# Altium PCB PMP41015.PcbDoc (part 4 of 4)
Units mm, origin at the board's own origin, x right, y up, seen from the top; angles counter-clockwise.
Board outline 173 x 85 mm, 2 copper layers (Top Layer, Bottom Layer), stack 1.575 mm thick; 89 components, 48 nets, 216 pads, 3458 vias.
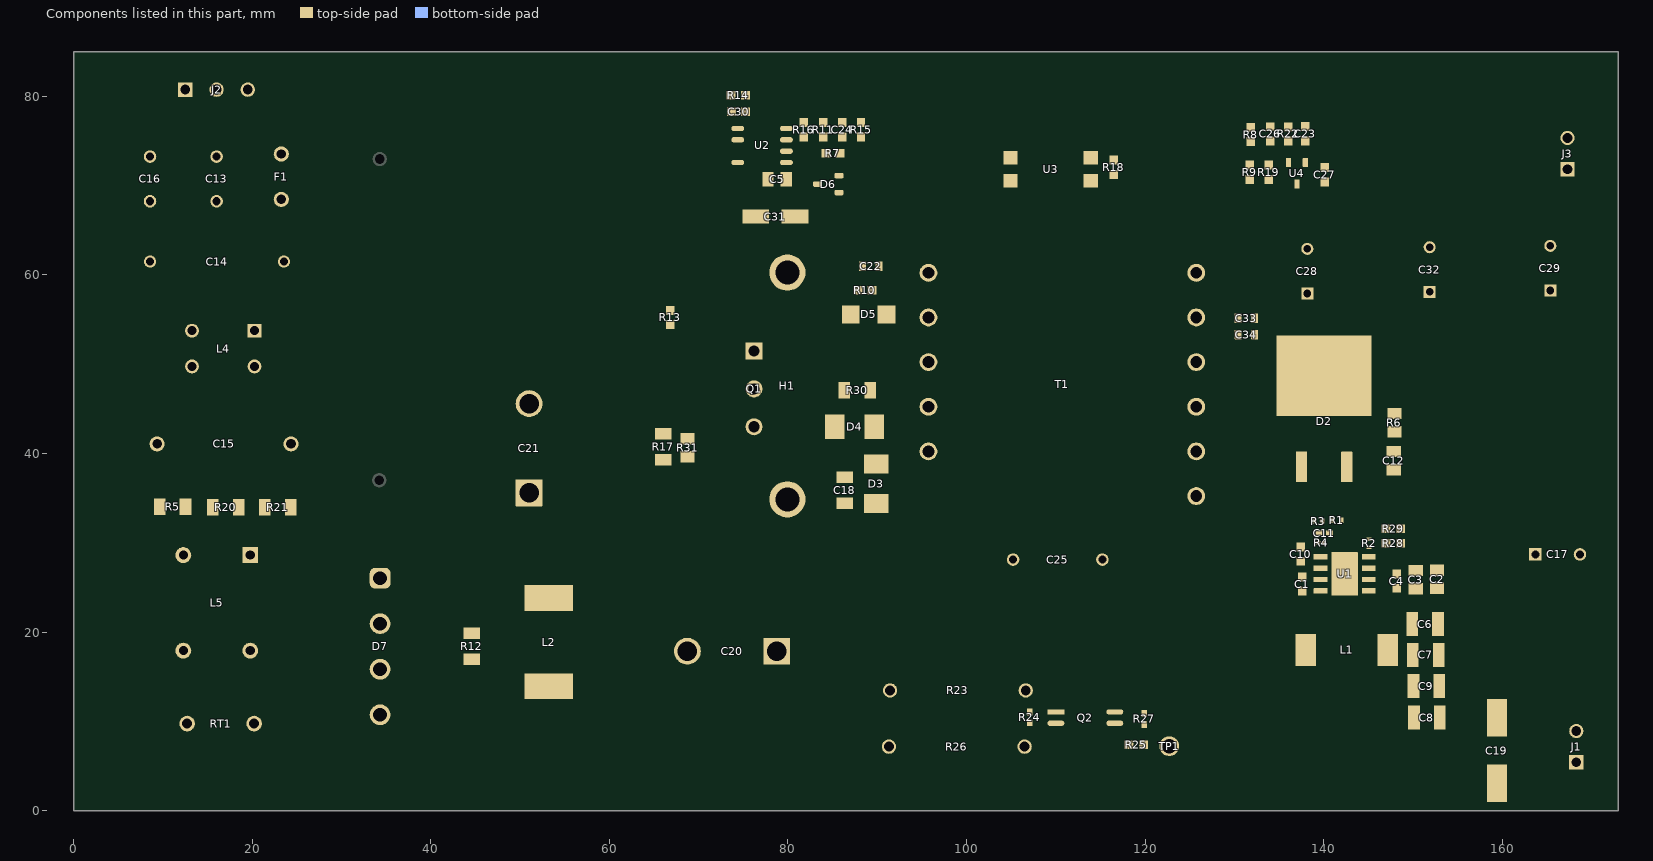
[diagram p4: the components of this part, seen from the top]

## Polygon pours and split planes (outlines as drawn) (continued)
+24V on Top Layer "TOP_LAYER_+24V_P107" (solid, remove dead copper, pour order 107): 159.029,42.8 149.962,42.8 149.962,28.489 149.064,27.592 144.244,27.567 144.244,25.883 165.608,25.883 165.608,31.524 171.978,31.524 171.978,73.101 163.627,73.101 163.627,65.964 167.157,65.964 167.157,60.782 159.029,60.782
PGND on Top Layer "TOP_LAYER_PGND_P042" (solid, remove dead copper, pour order 42): 29.388,24.426 37.084,24.426 37.084,83.657 29.388,83.657
+24V on Top Layer "TOP_LAYER_+24V_P097" (solid, remove dead copper, pour order 97): 128.246,43.355 128.244,57.022 132.105,60.884 159.08,60.884 159.08,54.178 158.27,54.178 158.27,43.355
PGND on Top Layer "TOP_LAYER_PGND_P090" (solid, remove dead copper, pour order 90): 63.525,39.54 63.525,17.412 64.783,16.154 71.857,16.154 73.635,17.932 73.635,26.34 73.635,38.973 72.298,40.31 64.295,40.31
NetQ1_3 on Top Layer "TOP_LAYER_NETQ1_3_P088" (solid, remove dead copper, pour order 88): 65.148,43.49 65.779,44.12 76.616,44.12 77.343,43.393 77.343,41.072 65.683,41.072 65.148,41.526
SGND on Top Layer "TOP_LAYER_SGND_P078" (solid, remove dead copper, pour order 78): 136.728,33.06 136.728,27.991 137.846,26.873 140.386,26.873 140.843,26.416 140.843,24.079 149.225,24.079 149.225,34.468 138.507,34.468
5V on Top Layer "TOP_LAYER_5V_P072" (solid, remove dead copper, pour order 72): 145.288,21.311 146.329,22.352 150.546,22.352 151.138,21.658 151.138,7.788 152.474,6.452 171.78,6.452 171.78,1.016 145.288,1.016 145.288,9.373
SGND on Top Layer "TOP_LAYER_SGND_P070" (solid, remove dead copper, pour order 70): 147.576,25.146 148.034,25.603 158.27,25.603 172.06,25.603 172.06,23.089 146.51,23.089 144.907,21.486 144.907,17.287 144.172,16.435 141.403,16.432 140.843,16.993 140.843,25.146
SGND on Top Layer "TOP_LAYER_SGND_P056" (solid, remove dead copper, pour order 56): 141.351,67.259 142.665,68.665 142.646,82.118 171.978,82.118 171.978,73.838 163.286,73.838 163.307,65.343 166.727,65.343 166.727,61.083 158.488,61.083 132.084,61.126 130.841,60.017 130.841,52.654 123.952,52.654 123.952,63.195 128.016,67.259
NetC12_1 on Top Layer "TOP_LAYER_NETC12_1_P052" (solid, remove dead copper, pour order 52): 123.686,37.401 124.727,36.36 145.599,36.36 145.599,42.8 128.37,42.8 126.947,44.224 126.913,47.244 123.927,47.244 123.612,46.93
SW on Top Layer "TOP_LAYER_SW_P024" (solid, remove dead copper, pour order 24): 139.249,16.154 139.249,23.37 140.056,24.177 140.056,24.943 139.802,25.197 137.135,25.197 136.754,24.816 136.754,16.154
no net on Top Layer "TOP_LAYER_NONET_P036" (solid, remove dead copper, pour order 36): 79.794,70.635 79.825,70.667 79.825,72.59
PGND on Top Layer "TOP_LAYER_PGND_P000" (solid, remove dead copper, pour order 0): 77.025,81.522 77.241,81.737 85.217,81.737 85.217,77.125 84.112,76.02 80.454,76.02 77.026,76.02
PGND on Top Layer "TOP_LAYER_PGND_P040" (solid, remove dead copper, pour order 40): 77.1,71.451 77.1,76.867 78.473,76.867 78.473,75.182 78.473,71.451
PGND on Top Layer "TOP_LAYER_PGND_P048" (solid, remove dead copper, pour order 48): 38.151,83.541 38.151,39.618 58.674,39.618 58.674,83.541

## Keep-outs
Keep-Out Layer:
  text ".Layer_Name" at 14.656,-21.806 h1.52

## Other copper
Top Layer:
  text ".Layer_Name" at 14.656,-21.806 h1.52
Bottom Layer:
  text ".Layer_Name" at 14.656,-21.806 h1.52

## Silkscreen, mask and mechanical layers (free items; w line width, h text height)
Top Overlay:
  text ".Layer_Name" at 14.656,-21.806 h1.52
Bottom Overlay:
  text ".Layer_Name" at 14.656,-21.806 h1.52
Top Paste:
  text ".Layer_Name" at 14.656,-21.806 h1.52
Bottom Paste:
  text ".Layer_Name" at 14.656,-21.806 h1.52
Top Solder:
  rectangle: 144.882,68.665 162.357,78.791
  text ".Layer_Name" at 14.656,-21.806 h1.52
  text ".Layer_Name" at 14.656,-21.806 h1.52
Bottom Solder:
  rectangle: 156.515,12.903 170.891,22.005
  rectangle: 160.02,36.36 165.862,52.313
  rectangle: 133.045,45.734 157.099,57.022
  rectangle: 144.574,68.986 161.315,78.715
  text ".Layer_Name" at 14.656,-21.806 h1.52
Drill Guide:
  text ".Layer_Name" at 14.656,-21.806 h1.52
M1 Board Outline:
  the board outline again, w0.254
  text ".Layer_Name" at 14.656,-21.806 h1.52
M2 Board Dimensions:
  rectangle: 0,-6.985 3.175,-3.81
  rectangle: 3.175,-10.16 12.7,-6.985
  lines w0.178: 0,-6.985 25.4,-6.985 ; 3.175,-10.16 3.175,-3.81 ; 6.35,-10.16 6.35,-3.81 ; 12.7,-10.16 12.7,-3.81 ; 19.05,-10.16 19.05,-3.81 ; 0,-10.16 25.4,-10.16 25.4,-3.81 0,-3.81 0,-10.16
  text ".Layer_Name" at 14.656,-21.806 h1.52
M3 3D STEP Top:
  text ".Layer_Name" at 14.656,-21.806 h1.52
M4 3D STEP Bottom:
  text ".Layer_Name" at 14.656,-21.806 h1.52
M5 Assembly Top:
  lines w0.254: -7.417,-23.626 160.223,-23.626 ; -7.417,-18.462 160.274,-18.462 ; -7.417,-13.297 -7.417,-28.791 94.31,-28.791 160.274,-28.791 160.274,-13.297 -7.404,-13.297 -7.404,-28.791 32.614,-28.791 ; 55.194,-28.791 55.194,-13.297 ; 87.376,-18.462 87.376,-13.297 ; 108.712,-18.462 108.712,-13.297 ; 124.511,-28.956 124.511,-23.804
  text "COMPONENTS MARKED 'DNP' SHOULD NOT BE POPULATED." at 29.299,-8.09 h1.52
  text "ASSEMBLY VARIANT:" at 29.286,-11.024 h1.52
  text ".VariantName" at 55.601,-11.024 h1.52
  text "PCB VIEWED FROM TOP SIDE" at -5.804,-16.654 h1.52
  text "BOARD #:" at 57.099,-16.654 h1.52
  text ".PRJ_Number" at 70.955,-16.654 h1.52
  text "REV:" at 92.405,-16.654 h1.52
  text ".PCB_Rev" at 99.809,-16.654 h1.52
  text "SVN REV:" at 113.69,-16.654 h1.52
  text ".VersionControl_RevNumber" at 126.543,-16.654 h1.52
  text "TID #:" at 57.099,-21.819 h1.52
  text ".TID" at 70.955,-21.819 h1.52
  text "PLOT NAME =" at -5.804,-27.034 h1.52
  text ".plot_File_Name" at 14.656,-27.034 h1.52
  text "GENERATED    :" at 57.15,-27.034 h1.52
  text ".Print_Date" at 79.235,-27.034 h1.52
  text ".Print_Time" at 97.752,-27.034 h1.52
  text "TEXAS INSTRUMENTS" at 129.87,-27.034 h1.52
M6 Assembly Bottom:
  lines w0.254: -7.429,-18.474 160.261,-18.474 ; -7.379,-23.639 160.261,-23.639 ; 28.334,-28.969 28.334,-23.817 ; 44.133,-18.474 44.133,-13.31 ; 65.468,-18.474 65.468,-13.31 ; 97.65,-28.804 97.65,-13.31 ; 120.231,-28.804 160.249,-28.804 160.249,-13.31 -7.429,-13.31 -7.429,-28.804 58.534,-28.804 160.261,-28.804 160.261,-13.31
  text "COMPONENTS MARKED 'DNP' SHOULD NOT BE POPULATED." at 154.991,-8.077 h1.52
  text ".VariantName" at 128.473,-11.024 h1.52
  text "ASSEMBLY VARIANT:" at 154.864,-11.024 h1.52
  text ".VersionControl_RevNumber" at 26.302,-16.667 h1.52
  text "SVN REV:" at 39.154,-16.667 h1.52
  text ".PCB_Rev" at 53.035,-16.667 h1.52
  text "REV:" at 60.439,-16.667 h1.52
  text ".PRJ_Number" at 81.89,-16.667 h1.52
  text "BOARD #:" at 95.745,-16.667 h1.52
  text "PCB VIEWED FROM BOTTOM SIDE" at 158.648,-16.667 h1.52
  text ".TID" at 81.89,-21.831 h1.52
  text "TID #:" at 95.745,-21.831 h1.52
  text "TEXAS INSTRUMENTS" at 22.974,-27.047 h1.52
  text ".Print_Time" at 55.093,-27.047 h1.52
  text ".Print_Date" at 73.609,-27.047 h1.52
  text "GENERATED    :" at 95.694,-27.047 h1.52
  text ".plot_File_Name" at 138.189,-27.047 h1.52
  text "PLOT NAME =" at 158.648,-27.047 h1.52
M9 Title Sheet:
  drawing of 57 lines, arcs and shapes, not listed
  text "1" at 18.792,204.127 h1.78
  text "2" at 82.182,204.127 h1.78
  text "3" at 145.411,204.127 h1.78
  text "4" at 209.08,204.127 h1.78
  text "5" at 272.555,204.127 h1.78
  text "6" at 336.182,204.127 h1.78
  text "A" at -10.579,175.095 h1.78
  text "A" at 365.341,175.095 h1.78
  text "B" at -10.579,114.643 h1.78
  text "B" at 365.341,114.643 h1.78
  text "C" at -10.579,54.318 h1.78
  text "C" at 365.341,54.318 h1.78
  text "PROJECT TITLE:" at 288.125,7.048 h1.14
  text ".PRJ_Title" at 289.395,3.662 h1.78
  text "DESIGNED FOR:" at 288.125,-0.597 h1.14
  text ".PRJ_Customer" at 289.395,-4.153 h1.78
  text "D" at -10.579,-5.88 h1.78
  text "D" at 365.341,-5.88 h1.78
  text "FILE NAME:" at 288.125,-8.217 h1.14
  text ".PCB_File_Name_No_Path" at 289.395,-11.265 h1.78
  text "Texas Instruments (TI) and/or its licensors do not warrant the accuracy or completeness of this specification" at 161.9,-15.376 h1.14
  text "ENGINEER:" at 288.125,-15.583 h1.14
  text "LAYOUT BY:" at 326.352,-15.583 h1.14
  text "or any information contained therein. TI and/or its licensors do not warrant that this design will meet" at 160.757,-18.237 h1.14
  text ".PRJ_Engineer" at 289.395,-19.52 h1.78
  text ".PCB_Layout" at 327.635,-19.52 h1.78
  text "the specifications, will be suitable for your application or fit for any particular purpose, or will operate in" at 160.757,-21.099 h1.14
  text ".Layer_Name" at 14.656,-21.806 h1.52
  text "ALTIUM DESIGNER VERSION:" at 326.352,-23.457 h1.14
  text "an implementation. TI and/or its licensors do not warrant that the design is production worthy. You should" at 160.757,-23.961 h1.14
  text "completely validate and test your design implementation to confirm the system functionality for your application." at 161.9,-26.822 h1.14
  text ".print_Scale" at 289.395,-26.843 h1.78
  text ".Application_BuildNumber" at 327.635,-26.843 h1.78
  text "1" at 18.792,-32.093 h1.78
  text "2" at 82.182,-32.093 h1.78
  text "3" at 145.411,-32.093 h1.78
  text "4" at 209.08,-32.093 h1.78
  text "5" at 272.555,-32.093 h1.78
  text "6" at 336.182,-32.093 h1.78
M10 Fab Notes:
  drawing of 189 lines, arcs and shapes, not listed
  text "DESIGN INFORMATION" at 314.503,161.447 h1.52
  text "MIN. TRACK WIDTH:" at 298.131,158.091 h1.52
  text "8" at 325.976,158.091 h1.52
  text "MIL" at 329.907,158.091 h1.52
  text "7.874" at 321.75,155 h1.52
  text "MIN. CLEARANCE:" at 298.131,154.938 h1.52
  text "MIL" at 329.907,154.938 h1.52
  text "MIN. VIA PAD SIZE:" at 298.131,151.785 h1.52
  text "24" at 325.214,151.785 h1.52
  text "MIL" at 329.907,151.785 h1.52
  text "0.05mm (2MIL)" at 315.784,148.486 h1.52
  text "MINIMUM ANNULAR RING" at 289.769,148.277 h1.52
  text "EXTERNAL" at 333.768,148.277 h1.52
  text "PER" at 294.849,145.48 h1.52
  text "IPC-D-275 CLASS 2 LEVEL C" at 300.437,145.48 h1.52
  text "MIL, HOLES" at 338.238,142.928 h1.52
  text "+/-" at 328.27,142.709 h1.52
  text "+/-" at 349.961,142.709 h1.52
  text "REGISTRATION TOLERANCES:" at 289.769,142.682 h1.52
  text "METAL" at 320.243,142.682 h1.52
  text "5" at 334.879,142.683 h1.52
  text "3" at 356.037,142.683 h1.52
  text "MIL" at 358.99,142.682 h1.52
  text "HOLE SIZE TOLERANCE (UNLESS OTHERWISE SPECIFIED):" at 289.769,140.185 h1.52
  text "+/-" at 349.961,140.112 h1.52
  text "3" at 356.037,140.085 h1.52
  text "MIL" at 358.99,140.085 h1.52
  text "MATERIAL:" at 287.87,136.589 h1.52
  text "FR-4 High Tg" at 312.926,133.324 h1.52
  text "X" at 309.257,133.122 h1.52
  text "FR-408" at 298.563,133.007 h1.52
  text "OTHER" at 336.358,133.007 h1.52
  text "62 MIL (1.6mm) +/-10%" at 306.694,129.374 h1.52
  text "X" at 303.643,129.312 h1.52
  text "THICKNESS:" at 289.769,129.165 h1.52
  text "OTHER" at 339.33,129.165 h1.52
  text "TOLERANCE:" at 289.769,125.652 h1.52
  text "X" at 311.314,125.652 h1.52
  text "ANSI IPC-6012 TYPE 3 CLASS 2" at 315.836,125.652 h1.52
  text "OTHER +/-" at 315.835,121.989 h1.52
  text "BOW & TWIST:" at 289.769,118.302 h1.52
  text "X" at 311.314,118.302 h1.52
  text "ANSI IPC-6012 TYPE 3 CLASS 2" at 315.836,118.302 h1.52
  text "OTHER +/-" at 315.835,114.576 h1.52
  text "DRILLING:" at 287.87,111.258 h1.52
  text "NC_DRILL FILES" at 332.599,108.586 h1.52
  text "REFERENCE:" at 289.769,108.486 h1.52
  text "X" at 306.463,108.484 h1.52
  text "AS SHOWN" at 310.984,108.486 h1.52
  text "X" at 329.348,108.486 h1.52
  text "OTHER" at 340.168,104.873 h1.52
  text "PTH COPPER THICKNESS:" at 289.761,104.783 h1.52
  text "X" at 318.697,104.783 h1.52
  text "20-30 um" at 321.948,104.783 h1.52
  text "BOARD FINISH:" at 287.87,101.034 h1.52
  text "SILKSCREEN:" at 291.812,98.237 h1.52
  text "X" at 316.14,98.237 h1.52
  text "TOP" at 319.112,98.237 h1.52
  text "X" at 329.094,98.237 h1.52
  text "BOTTOM" at 332.091,98.237 h1.52
  text "SILKSCREEN COLOR:" at 291.812,94.295 h1.52
  text "X" at 316.115,94.295 h1.52
  text "WHITE" at 319.112,94.295 h1.52
  text "OTHER" at 332.091,94.295 h1.52
  text "X" at 319.442,90.652 h1.52
  text "GREEN" at 322.439,90.652 h1.52
  text "OTHER" at 338.136,90.652 h1.52
  text "SOLDER RESIST COLOR:" at 291.812,90.477 h1.52
  text "X" at 319.442,86.734 h1.52
  text "MATTE" at 322.439,86.734 h1.52
  text "SEMI-GLOSS" at 338.125,86.717 h1.52
  text "IMMERSION GOLD (ENIG)" at 314.819,82.345 h1.52
  text "ENEPIG" at 348.793,82.162 h1.52
  text "SURFACE FINISH:" at 287.87,82.136 h1.52
  text "X" at 310.298,82.136 h1.52
  text "IMM. TIN/SILVER OR EQUIV" at 296.24,78.649 h1.52
  text "OTHER" at 332.599,78.549 h1.52
  text "ARRAY/PANEL:" at 287.87,74.602 h1.52
  text "CUT AND TRIM PER M1 BOARD OUTLINE" at 314.819,74.393 h1.52
  text "N.C. ROUTE" at 314.819,70.94 h1.52
  text "X" at 332.295,70.94 h1.52
  text "V. SCORE" at 336.816,70.94 h1.52
  text "CERTIFICATION:" at 287.87,67.66 h1.52
  text "MATERIALS AND WORKMANSHIP FOR ALL PCBS" at 306.285,67.66 h1.52
  text "TO MEET OR EXCEED THE REQUIREMENTS OF:" at 306.285,65.271 h1.52
  text "X" at 297.078,62.003 h1.52
  text "ANSI IPC-A-600F CLASS ->" at 300.329,62.003 h1.52
  text "X" at 342.188,62.003 h1.52
  text "2" at 344.982,62.003 h1.52
  text "1" at 336.981,61.965 h1.52
  text "3" at 353.973,61.965 h1.52
  text "X" at 317.702,58.252 h1.52
  text "RoHS" at 320.953,58.252 h1.52
  text "OTHER" at 337.321,58.252 h1.52
  text "PER ORDER" at 347.407,58.252 h1.52
  text "ALL BOARDS MUST MEET OR EXCEED UL94-V0 REQUIREMENTS." at 288.569,54.345 h1.52
  text "PCB MUST BEAR THE UL94V-0 UL REGISTERED MATERIAL ID NUMBER" at 288.569,51.397 h1.52
  text "ADDITIONAL REQUIREMENTS:" at 287.87,47.094 h1.52
  text "MICROSECTION:" at 289.769,44.373 h1.52
  text "YES" at 312.775,44.373 h1.52
  text "REQUIRED" at 334.657,40.707 h1.52
  text "BARE BOARD ELEC. TEST:" at 289.769,40.634 h1.52
  text "NONE" at 322.935,40.634 h1.52
  text "X" at 331.66,40.634 h1.52
  text "PER ORDER" at 349.693,40.634 h1.52
  text "XX MIL VIAS REQUIRE NON-CONDUCTIVE FILL AND PLANARIZE" at 294.04,35.428 h1.5
  text "XX MIL VIAS REQUIRE CONDUCTIVE FILL AND PLANARIZE" at 294.243,32.787 h1.52
  text "OUTER XX MIL TRACES REQUIRE 50 OHM SINGLE-ENDED IMPEDANCE" at 294.218,28.637 h1.47
  text "LAYER 2 & 3 (INNER LAYERS) XX MIL WIDE, XX MIL SPACE / TRACES REQUIRE 100 OHM DIFFERENTIAL IMPEDANCE" at 294.015,22.65 h1.52
  text ".Layer_Name" at 14.656,-21.806 h1.52
M11 Gerber Information:
  lines w0.254: -7.417,-23.626 160.223,-23.626 ; -7.417,-18.462 160.274,-18.462 ; -7.417,-13.297 -7.417,-28.791 94.31,-28.791 160.274,-28.791 160.274,-13.297 -7.404,-13.297 -7.404,-28.791 32.614,-28.791 ; 55.194,-28.791 55.194,-13.297 ; 87.376,-18.462 87.376,-13.297 ; 108.712,-18.462 108.712,-13.297 ; 124.511,-28.956 124.511,-23.804
  text "ALL ARTWORK VIEWED FROM TOP SIDE" at -5.804,-16.654 h1.52
  text "BOARD #:" at 57.099,-16.654 h1.52
  text ".PRJ_Number" at 70.955,-16.654 h1.52
  text "REV:" at 92.405,-16.654 h1.52
  text ".PCB_Rev" at 99.809,-16.654 h1.52
  text "SVN REV:" at 113.69,-16.654 h1.52
  text ".VersionControl_RevNumber" at 126.543,-16.654 h1.52
  text "LAYER NAME =" at -5.804,-21.806 h1.52
  text "TID #:" at 57.099,-21.819 h1.52
  text ".TID" at 70.955,-21.819 h1.52
  text "PLOT NAME =" at -5.804,-27.034 h1.52
  text ".plot_File_Name" at 14.656,-27.034 h1.52
  text "GENERATED    :" at 57.15,-27.034 h1.52
  text ".Print_Date" at 79.235,-27.034 h1.52
  text ".Print_Time" at 97.752,-27.034 h1.52
  text "TEXAS INSTRUMENTS" at 129.87,-27.034 h1.52
M12 Stackup:
  drawing of 191 lines, arcs and shapes, not listed
  text "Layer" at 249.469,193.165 h1.52
  text "Name" at 259.88,193.165 h1.52
  text "Material" at 283.496,193.165 h1.52
  text "Thickness" at 305.334,193.165 h1.52
  text "Constant" at 321.84,193.165 h1.52
  text "Board Layer Stack" at 336.314,193.165 h1.52
  text "Top Overlay" at 259.88,190.117 h1.52
  text "Top Solder" at 259.88,187.069 h1.52
  text "Solder Resist" at 283.496,187.069 h1.52
  text "0.40mil" at 305.334,187.069 h1.52
  text "3.5" at 321.84,187.069 h1.52
  text "1" at 249.469,184.021 h1.52
  text "Top Layer" at 259.88,184.021 h1.52
  text "1.40mil" at 305.334,184.021 h1.52
  text "Dielectric1" at 259.88,180.973 h1.52
  text "FR-4 High Tg" at 283.496,180.973 h1.52
  text "59.20mil" at 305.334,180.973 h1.52
  text "4.8" at 321.84,180.973 h1.52
  text "2" at 249.469,177.925 h1.52
  text "Bottom Layer" at 259.88,177.925 h1.52
  text "1.40mil" at 305.334,177.925 h1.52
  text "Bottom Solder" at 259.88,174.877 h1.52
  text "Solder Resist" at 283.496,174.877 h1.52
  text "0.40mil" at 305.334,174.877 h1.52
  text "3.5" at 321.84,174.877 h1.52
  text "Bottom Overlay" at 259.88,171.829 h1.52
  text ".Layer_Name" at 14.656,-21.806 h1.52
M13 Component Bodies Top:
  text ".Layer_Name" at 14.656,-21.806 h1.52
M14 Component Bodies Bottom:
  text ".Layer_Name" at 14.656,-21.806 h1.52
M15 Courtyards Top:
  text ".Layer_Name" at 14.656,-21.806 h1.52
M16 Courtyards Bottom:
  text ".Layer_Name" at 14.656,-21.806 h1.52
Drill Drawing:
  drawing of 184 lines, arcs and shapes, not listed
  text "Symbol" at 123.219,142.301 h1.83
  text "Quantity" at 130.853,142.301 h1.83
  text "Finished Hole Size" at 139.286,142.301 h1.83
  text "Plated" at 155.455,142.301 h1.83
  text "Hole Type" at 162.037,142.301 h1.83
  text "Drill Layer Pair" at 171.566,142.301 h1.83
  text "Hole Tolerance" at 189.964,142.301 h1.83
  text "2349" at 130.853,139.143 h1.52
  text "7.87mil (0.200mm)" at 139.286,139.143 h1.52
  text "PTH" at 155.455,139.143 h1.52
  text "Round" at 162.037,139.143 h1.52
  text "Top Layer - Bottom Layer" at 171.566,139.143 h1.52
  text "2" at 130.853,135.985 h1.52
  text "8.00mil (0.203mm)" at 139.286,135.985 h1.52
  text "PTH" at 155.455,135.985 h1.52
  text "Round" at 162.037,135.985 h1.52
  text "Top Layer - Bottom Layer" at 171.566,135.985 h1.52
  text "A" at 122.577,135.732 h1.4
  text "1066" at 130.853,132.828 h1.52
  text "13.00mil (0.330mm)" at 139.286,132.828 h1.52
  text "PTH" at 155.455,132.828 h1.52
  text "Round" at 162.037,132.828 h1.52
  text "Top Layer - Bottom Layer" at 171.566,132.828 h1.52
  text "41" at 130.853,129.67 h1.52
  text "13.01mil (0.330mm)" at 139.286,129.67 h1.52
  text "PTH" at 155.455,129.67 h1.52
  text "Round" at 162.037,129.67 h1.52
  text "Top Layer - Bottom Layer" at 171.566,129.67 h1.52
  text "B" at 122.577,129.416 h1.4
  text "8" at 130.853,126.512 h1.52
  text "33.47mil (0.850mm)" at 139.286,126.512 h1.52
  text "PTH" at 155.455,126.512 h1.52
  text "Round" at 162.037,126.512 h1.52
  text "Top Layer - Bottom Layer" at 171.566,126.512 h1.52
  text "8" at 130.853,123.354 h1.52
  text "35.43mil (0.900mm)" at 139.286,123.354 h1.52
  text "PTH" at 155.455,123.354 h1.52
  text "Round" at 162.037,123.354 h1.52
  text "Top Layer - Bottom Layer" at 171.566,123.354 h1.52
  text "4" at 130.853,120.197 h1.52
  text "39.37mil (1.000mm)" at 139.286,120.197 h1.52
  text "PTH" at 155.455,120.197 h1.52
  text "Round" at 162.037,120.197 h1.52
  text "Top Layer - Bottom Layer" at 171.566,120.197 h1.52
  text "4" at 130.853,117.039 h1.52
  text "40.00mil (1.016mm)" at 139.286,117.039 h1.52
  text "PTH" at 155.455,117.039 h1.52
  text "Round" at 162.037,117.039 h1.52
  text "Top Layer - Bottom Layer" at 171.566,117.039 h1.52
  text "2" at 130.853,113.881 h1.52
  text "41.34mil (1.050mm)" at 139.286,113.881 h1.52
  text "PTH" at 155.455,113.881 h1.52
  text "Round" at 162.037,113.881 h1.52
  text "Top Layer - Bottom Layer" at 171.566,113.881 h1.52
  text "2" at 130.853,110.723 h1.52
  text "42.08mil (1.069mm)" at 139.286,110.723 h1.52
  text "PTH" at 155.455,110.723 h1.52
  text "Round" at 162.037,110.723 h1.52
  text "Top Layer - Bottom Layer" at 171.566,110.723 h1.52
  text "15" at 130.853,107.566 h1.52
  text "43.31mil (1.100mm)" at 139.286,107.566 h1.52
  text "PTH" at 155.455,107.566 h1.52
  text "Round" at 162.037,107.566 h1.52
  text "Top Layer - Bottom Layer" at 171.566,107.566 h1.52
  text "3" at 130.853,104.408 h1.52
  text "49.21mil (1.250mm)" at 139.286,104.408 h1.52
  text "PTH" at 155.455,104.408 h1.52
  text "Round" at 162.037,104.408 h1.52
  text "Top Layer - Bottom Layer" at 171.566,104.408 h1.52
  text "11" at 130.853,101.25 h1.52
  text "51.97mil (1.320mm)" at 139.286,101.25 h1.52
  text "PTH" at 155.455,101.25 h1.52
  text "Round" at 162.037,101.25 h1.52
  text "Top Layer - Bottom Layer" at 171.566,101.25 h1.52
  text "4" at 130.853,98.093 h1.52
  text "61.02mil (1.550mm)" at 139.286,98.093 h1.52
  text "PTH" at 155.455,98.093 h1.52
  text "Round" at 162.037,98.093 h1.52
  text "Top Layer - Bottom Layer" at 171.566,98.093 h1.52
  text "1" at 130.853,94.935 h1.52
  text "63.00mil (1.600mm)" at 139.286,94.935 h1.52
  text "PTH" at 155.455,94.935 h1.52
  text "Round" at 162.037,94.935 h1.52
  text "Top Layer - Bottom Layer" at 171.566,94.935 h1.52
  text "4" at 130.853,91.777 h1.52
  text "86.61mil (2.200mm)" at 139.286,91.777 h1.52
  text "PTH" at 155.455,91.777 h1.52
  text "Round" at 162.037,91.777 h1.52
  text "Top Layer - Bottom Layer" at 171.566,91.777 h1.52
  text "2" at 130.853,88.619 h1.52
  text "106.30mil (2.700mm)" at 139.286,88.619 h1.52
  text "PTH" at 155.455,88.619 h1.52
  text "Round" at 162.037,88.619 h1.52
  text "Top Layer - Bottom Layer" at 171.566,88.619 h1.52
  text "+/-1.97mil" at 189.964,88.619 h1.52
  text "3526 Total" at 130.853,85.462 h1.52
  text ".Layer_Name" at 14.656,-21.806 h1.52
M17 Embedded Cavity:
  text ".Layer_Name" at 14.656,-21.806 h1.52
M18 Embedded Assembly:
  text ".Layer_Name" at 14.656,-21.806 h1.52
M19 Embedded Keepout:
  text ".Layer_Name" at 14.656,-21.806 h1.52

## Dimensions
0,-10.16 to 25.4,-10.16 on M2 Board Dimensions
0,0 to 173,85 on M2 Board Dimensions
0,0 to 173,0 on M2 Board Dimensions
